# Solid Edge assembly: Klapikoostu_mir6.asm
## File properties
Author: Türk
Template: Iso Assembly.asm
Last saved by: Türk
Revision: 3
Application: Solid Edge
Username: Türk
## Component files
Klapipuks.par
Klapp.par
Klapi vedru_mir2.par
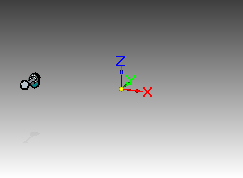
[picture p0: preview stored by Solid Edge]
